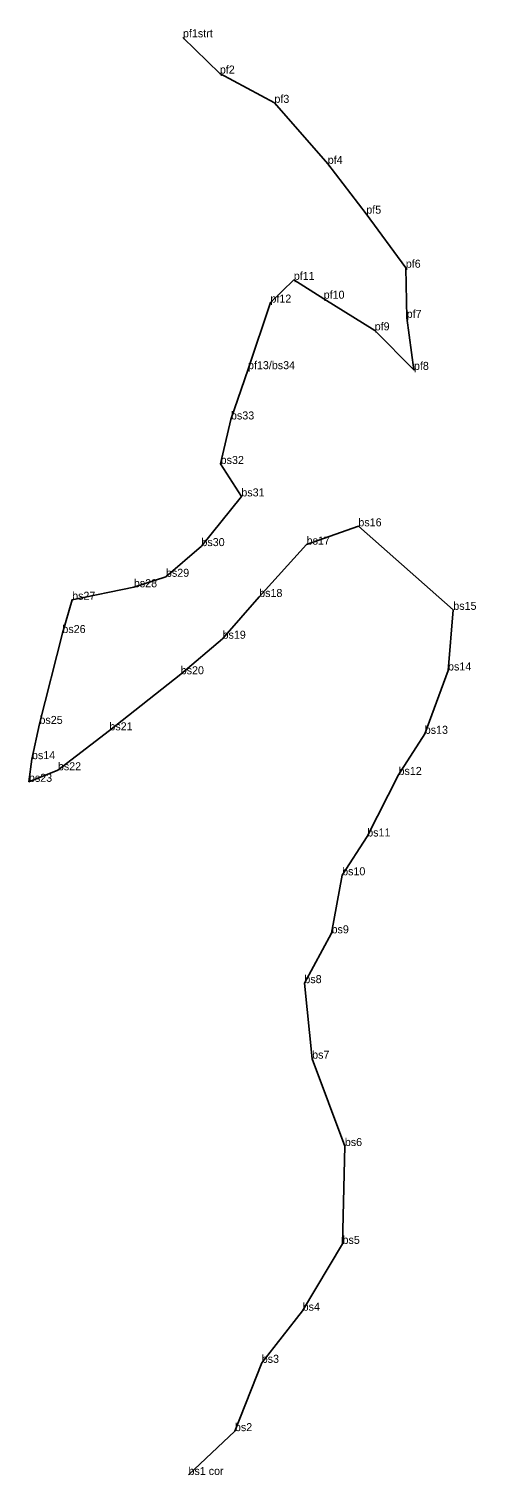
# Model space of a CAD drawing. Extents: x 2072529 to 2267990, y 436423 to 470008.
# Drawn here: x 2232576 to 2232911, y 437812 to 438897 of the extents above; entities that cross this region are included whole.
import ezdxf

# ---------------------------------------------------------------- set-up
doc = ezdxf.new("R2010")
doc.units = 0
doc.layers.add('Level 3', color=7, linetype='Continuous')
doc.layers.add('Old_Level_52', color=7, linetype='Continuous')

msp = doc.modelspace()

# ---------------------------------------------------------------- linework, layer by layer
at = {"layer": 'Level 3'}
for p, q in [((2232691.444, 438890.389), (2232691.444, 438890.389)), ((2232719.094, 438863.22), (2232719.094, 438863.22)), ((2232759.976, 438841.273), (2232759.976, 438841.273)), ((2232799.951, 438795.466), (2232799.951, 438795.466)), ((2232828.827, 438758.143), (2232828.827, 438758.143)), ((2232774.501, 438708.528), (2232774.501, 438708.528)), ((2232858.429, 438717.637), (2232858.429, 438717.637)), ((2232756.996, 438691.504), (2232756.996, 438691.504)), ((2232796.896, 438694.397), (2232796.896, 438694.397)), ((2232859.094, 438680.018), (2232859.094, 438680.018)), ((2232835.136, 438670.666), (2232835.136, 438670.666)), ((2232740.188, 438641.561), (2232740.188, 438641.561)), ((2232864.537, 438641.034), (2232864.537, 438641.034)), ((2232727.429, 438603.865), (2232727.429, 438603.865)), ((2232719.688, 438570.481), (2232719.688, 438570.481)), ((2232735.194, 438546.164), (2232735.194, 438546.164)), ((2232822.886, 438523.733), (2232822.886, 438523.733)), ((2232705.271, 438508.904), (2232705.271, 438508.904)), ((2232784.134, 438510.061), (2232784.134, 438510.061)), ((2232678.695, 438485.895), (2232678.695, 438485.895)), ((2232608.369, 438468.674), (2232608.369, 438468.674)), ((2232654.649, 438478.075), (2232654.649, 438478.075)), ((2232748.557, 438470.738), (2232748.557, 438470.738)), ((2232894.029, 438461.097), (2232894.029, 438461.097)), ((2232601.065, 438443.708), (2232601.065, 438443.708)), ((2232721.109, 438439.442), (2232721.109, 438439.442)), ((2232890.086, 438415.643), (2232890.086, 438415.643)), ((2232689.769, 438412.804), (2232689.769, 438412.804)), ((2232583.9, 438375.569), (2232583.9, 438375.569)), ((2232636.283, 438370.742), (2232636.283, 438370.742)), ((2232872.641, 438368.14), (2232872.641, 438368.14)), ((2232578.271, 438349.146), (2232578.271, 438349.146)), ((2232597.718, 438340.801), (2232597.718, 438340.801)), ((2232576.01, 438332.148), (2232576.01, 438332.148)), ((2232852.983, 438337.308), (2232852.983, 438337.308)), ((2232829.521, 438291.16), (2232829.521, 438291.16)), ((2232810.711, 438262.061), (2232810.711, 438262.061)), ((2232802.815, 438218.555), (2232802.815, 438218.555)), ((2232782.42, 438181.189), (2232782.42, 438181.189)), ((2232788.238, 438124.548), (2232788.238, 438124.548)), ((2232812.739, 438059.039), (2232812.739, 438059.039)), ((2232811.026, 437985.675), (2232811.026, 437985.675)), ((2232781.143, 437935.578), (2232781.143, 437935.578)), ((2232750.466, 437896.503), (2232750.466, 437896.503)), ((2232730.384, 437845.273), (2232730.384, 437845.273)), ((2232695.572, 437812.406), (2232695.572, 437812.406))]:
    msp.add_line(p, q, dxfattribs=at)
at = {"layer": 'Old_Level_52'}
msp.add_lwpolyline([(2232691.444, 438890.389), (2232719.094, 438863.22), (2232759.976, 438841.273), (2232799.951, 438795.466), (2232828.827, 438758.143), (2232858.429, 438717.637), (2232859.094, 438680.018), (2232864.537, 438641.034), (2232835.136, 438670.666), (2232796.896, 438694.397), (2232774.501, 438708.528), (2232756.996, 438691.504), (2232740.188, 438641.561), (2232727.429, 438603.865), (2232719.688, 438570.481), (2232735.194, 438546.164), (2232705.271, 438508.904), (2232678.695, 438485.895), (2232654.649, 438478.075), (2232608.369, 438468.674), (2232601.065, 438443.708), (2232583.9, 438375.569), (2232578.271, 438349.146), (2232576.01, 438332.148), (2232597.718, 438340.801), (2232636.283, 438370.742), (2232689.769, 438412.804), (2232721.109, 438439.442), (2232748.557, 438470.738), (2232784.134, 438510.061), (2232822.886, 438523.733), (2232894.029, 438461.097), (2232890.086, 438415.643), (2232872.641, 438368.14), (2232852.983, 438337.308), (2232829.521, 438291.16), (2232810.711, 438262.061), (2232802.815, 438218.555), (2232782.42, 438181.189), (2232788.238, 438124.548), (2232812.739, 438059.039), (2232811.026, 437985.675), (2232781.143, 437935.578), (2232750.466, 437896.503), (2232730.384, 437845.273), (2232695.572, 437812.406)], dxfattribs=at)

# ---------------------------------------------------------------- texts
for s, p in [('pf1strt', (2232691.444, 438890.389)), ('pf2', (2232719.094, 438863.22)), ('pf3', (2232759.976, 438841.273)), ('pf4', (2232799.951, 438795.466)), ('pf5', (2232828.827, 438758.143)), ('pf6', (2232858.429, 438717.637)), ('pf11', (2232774.501, 438708.528)), ('pf12', (2232756.996, 438691.504)), ('pf10', (2232796.896, 438694.397)), ('pf7', (2232859.094, 438680.018)), ('pf9', (2232835.136, 438670.666)), ('pf13/bs34', (2232740.188, 438641.561)), ('pf8', (2232864.537, 438641.034)), ('bs33', (2232727.429, 438603.865)), ('bs32', (2232719.688, 438570.481)), ('bs31', (2232735.194, 438546.164)), ('bs16', (2232822.886, 438523.733)), ('bs30', (2232705.271, 438508.904)), ('bs17', (2232784.134, 438510.061)), ('bs29', (2232678.695, 438485.895)), ('bs28', (2232654.649, 438478.075)), ('bs27', (2232608.369, 438468.674)), ('bs18', (2232748.557, 438470.738)), ('bs15', (2232894.029, 438461.097)), ('bs26', (2232601.065, 438443.708)), ('bs19', (2232721.109, 438439.442)), ('bs20', (2232689.769, 438412.804)), ('bs14', (2232890.086, 438415.643)), ('bs25', (2232583.9, 438375.569)), ('bs21', (2232636.283, 438370.742)), ('bs13', (2232872.641, 438368.14)), ('bs14', (2232578.271, 438349.146)), ('bs22', (2232597.718, 438340.801)), ('bs12', (2232852.983, 438337.308)), ('bs23', (2232576.01, 438332.148)), ('bs11', (2232829.521, 438291.16)), ('bs10', (2232810.711, 438262.061)), ('bs9', (2232802.815, 438218.555)), ('bs8', (2232782.42, 438181.189)), ('bs7', (2232788.238, 438124.548)), ('bs6', (2232812.739, 438059.039)), ('bs5', (2232811.026, 437985.675)), ('bs4', (2232781.143, 437935.578)), ('bs3', (2232750.466, 437896.503)), ('bs2', (2232730.384, 437845.273)), ('bs1 cor', (2232695.572, 437812.406))]:
    msp.add_text(s, height=6).set_placement(p)

doc.saveas('drawing.dxf')
